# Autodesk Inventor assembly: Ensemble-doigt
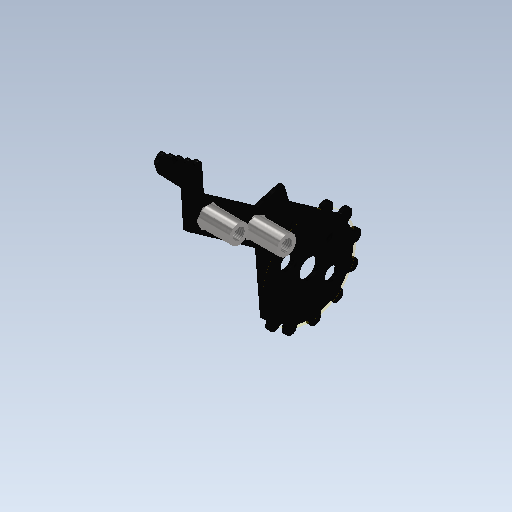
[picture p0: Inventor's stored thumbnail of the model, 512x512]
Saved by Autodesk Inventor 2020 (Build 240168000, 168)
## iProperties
Created: 2021-10
Part Number: Ensemble-doigt
Document SubType Name: Assembly
Designer: bruno
Author: bruno
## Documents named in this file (3)
- C:\Users\bruno\Documents\1-Cours-2021-22\1SI\Challenge-2021\Pince-Inventor\Ensemble-doigt.iam
- C:\Users\bruno\Documents\1-Cours-2021-22\1SI\Challenge-2021\Pince-Inventor\pince.ipt
- C:\Users\bruno\Documents\1-Cours-2021-22\1SI\Challenge-2021\Pince-Inventor\Ecrou-support.ipt
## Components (3 placed, 2 different names)
1. pince:1 — Placage:1, Placage:2, Affleurement:1, Placage:3, Placage:4, Affleurement:2, Placage:5
2. Ecrou-support:1 — Placage:1, Placage:2, Affleurement:1, Placage:3
3. Ecrou-support:2 — Placage:4, Affleurement:2, Placage:5
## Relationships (7: Mate 5, Flush 2)
- Placage:1 [Mate]: pince:1 ↔ Ecrou-support:1
- Placage:2 [Mate]: pince:1 ↔ Ecrou-support:1
- Affleurement:1 [Flush]: pince:1 ↔ Ecrou-support:1
- Placage:3 [Mate]: pince:1 ↔ Ecrou-support:1
- Placage:4 [Mate]: pince:1 ↔ Ecrou-support:2
- Affleurement:2 [Flush]: pince:1 ↔ Ecrou-support:2
- Placage:5 [Mate]: pince:1 ↔ Ecrou-support:2
